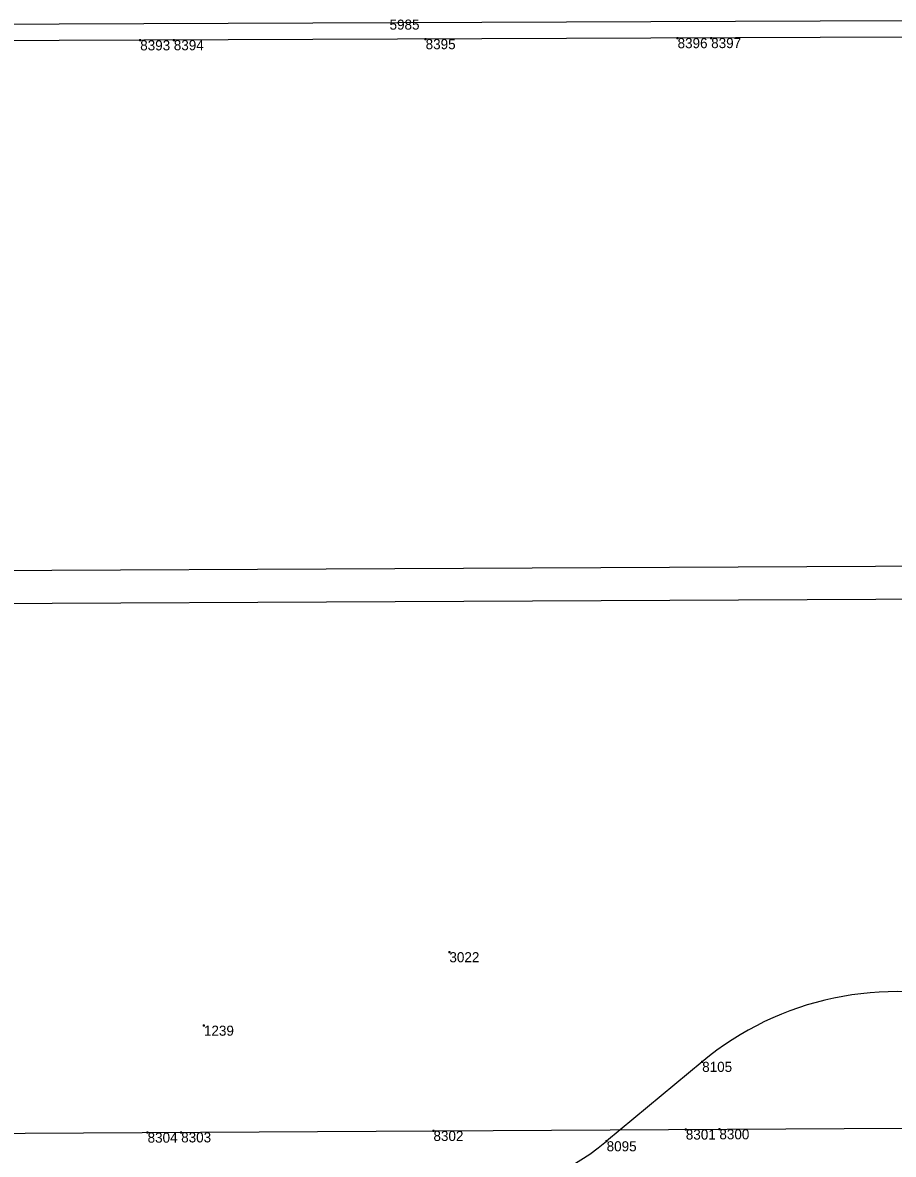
# Model space of a CAD drawing. Extents: x 2145146 to 2158053, y 137507 to 150829.
# Drawn here: x 2151391 to 2152428, y 145617 to 146965 of the extents above; entities that cross this region are included whole.
import ezdxf

# ---------------------------------------------------------------- set-up
doc = ezdxf.new("R2010")
doc.units = 0
for name, color, linetype in [('ALIGN_Cogo Points', 7, 'Continuous'), ('ALIGN_ROW Line', 7, 'Continuous'), ('PLSS_Block Line', 7, 'Continuous'), ('PLSS_Section Line', 7, 'Continuous')]:
    doc.layers.add(name, color=color, linetype=linetype)

msp = doc.modelspace()

# ---------------------------------------------------------------- linework, layer by layer
at = {"layer": 'ALIGN_Cogo Points'}
for points in [[(2151531.3, 146943.7), (2151531.3, 146944.9), (2151531.3, 146943.7), (2151530.1, 146943.7), (2151531.3, 146943.7), (2151531.3, 146942.5), (2151531.3, 146943.7), (2151532.5, 146943.7)], [(2151571.3, 146943.9), (2151571.3, 146945.1), (2151571.3, 146943.9), (2151570.1, 146943.9), (2151571.3, 146943.9), (2151571.3, 146942.7), (2151571.3, 146943.9), (2151572.5, 146943.9)], [(2151871.3, 146945.1), (2151871.3, 146946.3), (2151871.3, 146945.1), (2151870.1, 146945.1), (2151871.3, 146945.1), (2151871.3, 146943.9), (2151871.3, 146945.1), (2151872.5, 146945.1)], [(2152171.4, 146946.3), (2152171.4, 146947.5), (2152171.4, 146946.3), (2152170.2, 146946.3), (2152171.4, 146946.3), (2152171.4, 146945.1), (2152171.4, 146946.3), (2152172.6, 146946.3)], [(2152211.4, 146946.4), (2152211.4, 146947.6), (2152211.4, 146946.4), (2152210.2, 146946.4), (2152211.4, 146946.4), (2152211.4, 146945.2), (2152211.4, 146946.4), (2152212.6, 146946.4)], [(2151899.6, 145857.5), (2151899.6, 145858.7), (2151899.6, 145857.5), (2151898.4, 145857.5), (2151899.6, 145857.5), (2151899.6, 145856.3), (2151899.6, 145857.5), (2151900.8, 145857.5)], [(2151607.2, 145770), (2151607.2, 145771.2), (2151607.2, 145770), (2151606, 145770), (2151607.2, 145770), (2151607.2, 145768.8), (2151607.2, 145770), (2151608.4, 145770)], [(2152200.7, 145726.9), (2152200.7, 145728.1), (2152200.7, 145726.9), (2152199.5, 145726.9), (2152200.7, 145726.9), (2152200.7, 145725.7), (2152200.7, 145726.9), (2152201.9, 145726.9)], [(2151540.1, 145642.6), (2151540.1, 145643.8), (2151540.1, 145642.6), (2151538.9, 145642.6), (2151540.1, 145642.6), (2151540.1, 145641.4), (2151540.1, 145642.6), (2151541.3, 145642.6)], [(2151580.1, 145642.9), (2151580.1, 145644.1), (2151580.1, 145642.9), (2151578.9, 145642.9), (2151580.1, 145642.9), (2151580.1, 145641.7), (2151580.1, 145642.9), (2151581.3, 145642.9)], [(2151880.6, 145644.6), (2151880.6, 145645.8), (2151880.6, 145644.6), (2151879.4, 145644.6), (2151880.6, 145644.6), (2151880.6, 145643.4), (2151880.6, 145644.6), (2151881.8, 145644.6)], [(2152181.2, 145646.3), (2152181.2, 145647.5), (2152181.2, 145646.3), (2152180, 145646.3), (2152181.2, 145646.3), (2152181.2, 145645.1), (2152181.2, 145646.3), (2152182.4, 145646.3)], [(2152221.2, 145646.6), (2152221.2, 145647.8), (2152221.2, 145646.6), (2152220, 145646.6), (2152221.2, 145646.6), (2152221.2, 145645.4), (2152221.2, 145646.6), (2152222.4, 145646.6)], [(2152086.9, 145632.3), (2152086.9, 145633.5), (2152086.9, 145632.3), (2152085.7, 145632.3), (2152086.9, 145632.3), (2152086.9, 145631.1), (2152086.9, 145632.3), (2152088.1, 145632.3)]]:
    msp.add_lwpolyline(points, dxfattribs=at)
at = {"layer": 'ALIGN_ROW Line'}
msp.add_lwpolyline([(2152200.7, 145726.9), (2152200.7, 145726.9), (2152086.9, 145632.3), (2152086.9, 145632.3)], dxfattribs=at)
for centre, radius, start, end in [((2152431.8, 145449), 361.5, 73.9727, 129.7426), ((2151899.6, 145857.5), 292.9, 270.3251, 309.7426)]:
    msp.add_arc(centre, radius, start, end, dxfattribs=at)
at = {"layer": 'PLSS_Block Line'}
for points in [[(2150931, 146961.3), (2153549.3, 146971.8)], [(2153549.4, 146951.8), (2150931.1, 146941.3)], [(2150934.9, 146310.3), (2153552, 146323)], [(2153552.1, 146283), (2150935.2, 146270.3)]]:
    msp.add_lwpolyline(points, dxfattribs=at)
at = {"layer": 'PLSS_Section Line'}
msp.add_lwpolyline([(2150905.8, 145639), (2153554.7, 145654.3)], dxfattribs=at)

# ---------------------------------------------------------------- texts
at = {"layer": 'ALIGN_Cogo Points'}
for s, p in [('5985', (2151828.3, 146956.4)), ('8393', (2151531.3, 146931.7)), ('8394', (2151571.3, 146931.9)), ('8395', (2151871.3, 146933.1)), ('8396', (2152171.4, 146934.3)), ('8397', (2152211.4, 146934.4)), ('3022', (2151899.6, 145845.5)), ('1239', (2151607.2, 145758)), ('8105', (2152200.7, 145714.9)), ('8304', (2151540.1, 145630.6)), ('8303', (2151580.1, 145630.9)), ('8302', (2151880.6, 145632.6)), ('8301', (2152181.2, 145634.3)), ('8300', (2152221.2, 145634.6)), ('8095', (2152086.9, 145620.3))]:
    msp.add_text(s, height=12, dxfattribs=at).set_placement(p)

doc.saveas('drawing.dxf')
